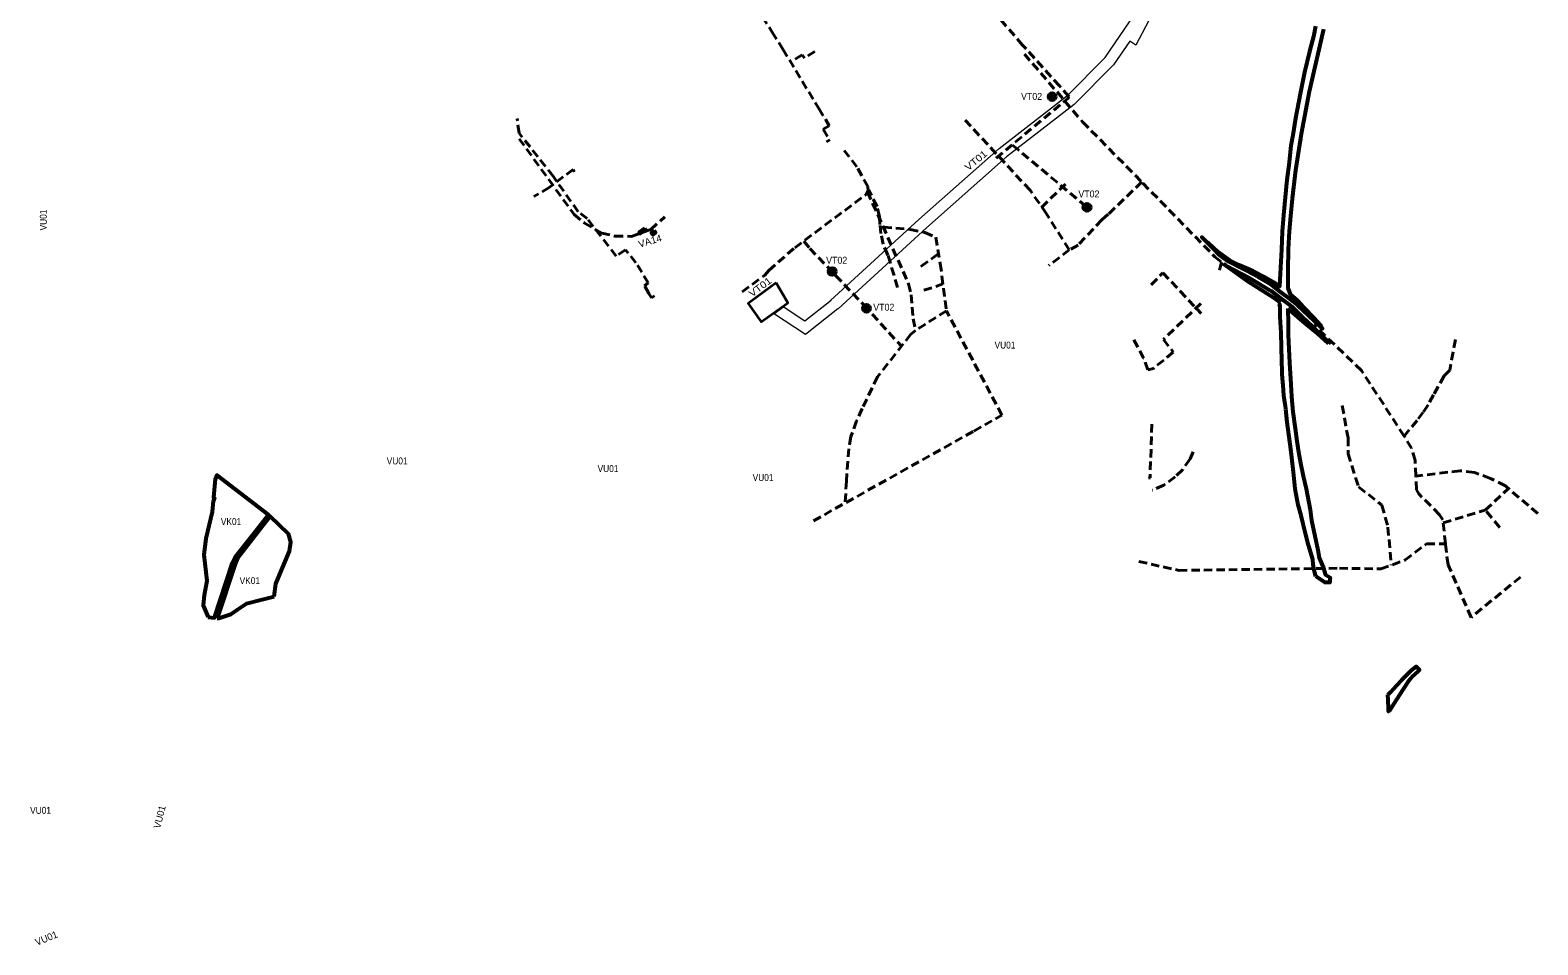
# Model space of a CAD drawing. Extents: x -650145 to -642675, y -1074338 to -1066724.
# Drawn here: x -648976 to -644627, y -1074338 to -1071699 of the extents above; entities that cross this region are included whole.
import ezdxf

# ---------------------------------------------------------------- set-up
doc = ezdxf.new("R2010")
doc.units = 0
doc.header["$LTSCALE"] = 8
doc.linetypes.add('MEDIUM_DASHED', pattern=[4.5, 3, -1.5])
for name, color, linetype in [('1', 7, 'Continuous'), ('17', 7, 'Continuous'), ('2', 7, 'Continuous'), ('3', 7, 'Continuous')]:
    doc.layers.add(name, color=color, linetype=linetype)
for name, color, linetype, lineweight in [('12', 7, 'MEDIUM_DASHED', 40), ('15', 7, 'Continuous', 13), ('45', 7, 'Continuous', 53), ('60', 7, 'Continuous', 53)]:
    doc.layers.add(name, color=color, linetype=linetype, lineweight=lineweight)

msp = doc.modelspace()

# ---------------------------------------------------------------- hatches: boundary and pattern name
at = {"layer": '15'}
for points in [[(-646016.453, -1071890.987, 1), (-646039.978, -1071890.987, 1)], [(-645916.109, -1072210.132, 1), (-645939.634, -1072210.132, 1)], [(-646651.182, -1072395.364, 1), (-646674.706, -1072395.364, 1)], [(-646551.973, -1072501.882, 1), (-646575.498, -1072501.882, 1)]]:
    msp.add_hatch(color=256, dxfattribs=at).paths.add_polyline_path(points)
at = {"layer": '60'}
for points in [[(-647203.48, -1072271.1), (-647219.86, -1072283.16), (-647217.95, -1072285.83), (-647201.52, -1072273.8)], [(-647175.95, -1072277.72), (-647183.77, -1072283.6), (-647179.89, -1072288.9), (-647172.06, -1072283.01)]]:
    msp.add_hatch(color=256, dxfattribs=at).paths.add_polyline_path(points)

# ---------------------------------------------------------------- linework, layer by layer
at = {"layer": '12'}
for p, q in [((-646142.308, -1072031.286), (-645934.368, -1072204.655)), ((-645990.194, -1072143.593), (-646067.454, -1072218.303)), ((-646406.679, -1072380.519), (-646355.921, -1072344.291)), ((-646398.36, -1072449.736), (-646343.369, -1072431.172)), ((-644737.523, -1073134.312), (-644778.948, -1073083.582))]:
    msp.add_line(p, q, dxfattribs=at)
for points in [[(-646901.7, -1071599.29), (-646836.01, -1071704.74), (-646804.94, -1071754.31)], [(-645979.173, -1071891.235), (-646007.318, -1071860.17), (-646113.522, -1071742.176), (-646203.196, -1071638.82), (-646210.712, -1071621.148)], [(-646804.94, -1071754.31), (-646701.24, -1071925.46), (-646671.37, -1071974.86)], [(-646712.71, -1071760.64), (-646743.06, -1071780.15), (-646749.35, -1071770.55), (-646782.673, -1071791.06)], [(-646108.34, -1071768.288), (-645991.774, -1071903.675), (-645940.8, -1071963.54), (-645766.873, -1072140.424), (-645559.153, -1072352.891), (-645539.728, -1072368.513), (-645547.013, -1072398.199)], [(-646190.163, -1072068.09), (-645983.794, -1071896.963), (-645979.173, -1071891.234)], [(-647369.65, -1072242.58), (-647395.603, -1072222.827), (-647467.645, -1072120.835), (-647565.59, -1071996.178), (-647571.937, -1071954.126)], [(-646671.37, -1071974.86), (-646688.66, -1071985.16), (-646669.77, -1072015.67), (-646679.35, -1072021.71)], [(-645978.908, -1072332.844), (-646044.53, -1072228.907), (-646091.859, -1072161.141), (-646284.4, -1071953.541)], [(-647565.274, -1072012.581), (-647407.42, -1072230.889), (-647378.312, -1072255.368), (-647327.486, -1072284.458), (-647289.597, -1072293.583), (-647241.628, -1072293.997), (-647186.201, -1072273.818), (-647145.51, -1072238.04)], [(-646922.495, -1072453.643), (-646857.191, -1072406.111), (-646845.696, -1072392.061), (-646770.684, -1072326.695), (-646564.651, -1072173.134), (-646559.323, -1072162.51), (-646560.242, -1072150.62), (-646591.477, -1072093.57), (-646627.948, -1072046.396)], [(-647405.694, -1072108.1), (-647409.897, -1072100.921), (-647478.896, -1072153.329), (-647523.403, -1072178.874)], [(-646515.621, -1072316.407), (-646522.296, -1072286.272), (-646525.05, -1072259.936), (-646526.73, -1072237.276), (-646533.563, -1072207.871), (-646557.282, -1072161.242)], [(-645770.117, -1072137.125), (-645867.081, -1072230.375), (-645887.539, -1072249.441)], [(-646560.829, -1072165.418), (-646442.617, -1072430.974), (-646435.336, -1072462.744), (-646429.379, -1072531.58), (-646422.811, -1072565.755), (-646435.637, -1072576.085), (-646531.76, -1072698.93), (-646576.398, -1072790.696), (-646592.362, -1072826.343), (-646608.607, -1072871.571), (-646614.559, -1072906.613), (-646622.02, -1072999.792), (-646625.456, -1073063.469)], [(-647191.37, -1072458.86), (-647204.41, -1072436.35), (-647193.17, -1072428.14), (-647228.9, -1072369.98), (-647259.29, -1072332.91), (-647286.03, -1072350.98), (-647368.027, -1072244.683)], [(-645884.618, -1072246.363), (-645953.602, -1072319.058), (-645978.908, -1072332.844), (-646038.138, -1072377.943)], [(-646515.068, -1072268.004), (-646438.375, -1072274.017), (-646395.81, -1072282.852), (-646364.347, -1072296.336), (-646351.055, -1072371.983), (-646333.32, -1072508.549)], [(-646744.92, -1072307.492), (-646727.261, -1072328.683), (-646572.036, -1072491.987), (-646462.937, -1072610.974)], [(-646474.01, -1072441.461), (-646502.208, -1072348.07), (-646515.621, -1072316.407)], [(-645742.473, -1072433.786), (-645709.258, -1072399.404), (-645598.422, -1072516.199)], [(-647175.32, -1072466), (-647184.36, -1072470.98), (-647191.37, -1072458.86)], [(-646716.85, -1073114.625), (-646254.197, -1072855.664), (-646173.155, -1072809.893), (-646333.32, -1072508.549), (-646422.811, -1072565.755)], [(-645599.642, -1072487.459), (-645707.673, -1072591.746), (-645678.856, -1072628.004), (-645736.077, -1072674.835), (-645752.766, -1072679.471), (-645764.412, -1072645.375), (-645793.32, -1072590.47)], [(-644677.063, -1073276.773), (-644820.09, -1073393.239), (-644886.431, -1073241.755), (-644894.218, -1073180.725), (-644901.367, -1073111.484), (-644910.953, -1073097.104), (-644970.414, -1073037.091), (-644977.617, -1073024.956), (-644979.519, -1072985.65), (-644981.225, -1072940.656), (-644991.691, -1072905.052), (-645013.264, -1072869.98), (-645136.284, -1072680.783), (-645273.573, -1072549.71)], [(-644865.163, -1072591.801), (-644881.47, -1072679.739), (-644897.776, -1072696.046), (-644928.014, -1072751.285)], [(-644928.014, -1072751.285), (-644944.228, -1072780.29), (-644958.247, -1072801.452), (-644975.175, -1072824.929), (-645013.264, -1072869.98)], [(-645191.679, -1072782.461), (-645175.001, -1072875.23), (-645175.001, -1072921.093), (-645144.773, -1073016.989), (-645077.02, -1073069.106), (-645059.861, -1073133.007), (-645050.18, -1073242.481)], [(-645740.627, -1072835.69), (-645745.906, -1072985.427), (-645745.265, -1072991.028), (-645750.784, -1072992.05)], [(-645621.405, -1072915.798), (-645630.523, -1072936.275), (-645652.44, -1072967.63), (-645673.716, -1072987.946), (-645706.351, -1073011.942), (-645739.675, -1073026.324)], [(-644627.418, -1073093.922), (-644720.94, -1073014.135), (-644763.53, -1072992.287), (-644810.544, -1072975.14), (-644851.751, -1072970.162), (-644979.519, -1072985.65)], [(-644900.454, -1073120.324), (-644778.948, -1073083.582), (-644712.07, -1073021.703)], [(-645777.988, -1073231.981), (-645662.45, -1073257.758), (-645199.545, -1073251.421), (-645080.605, -1073253.501), (-645010.848, -1073228.236), (-644948.284, -1073180.725), (-644894.218, -1073180.725)]]:
    msp.add_lwpolyline(points, dxfattribs=at)
at = {"layer": '15', "lineweight": 35}
msp.add_line((-646832.318, -1072516.145), (-646804.328, -1072496.262), dxfattribs=at)
at = {"layer": '15'}
for points in [[(-645985.984, -1071889.912), (-645875.751, -1071778.476), (-645805.025, -1071675.361), (-645627.872, -1071341.184), (-645225.385, -1071341.796), (-645184.278, -1071232.417)], [(-645184.278, -1071232.417), (-645183.56, -1071242.5), (-645178.87, -1071266.352), (-645207.234, -1071341.824), (-645170.274, -1071341.88), (-645167.04, -1071373.884), (-645592.784, -1071373.238), (-645786.781, -1071742.105), (-645804.579, -1071731.285)], [(-645804.579, -1071731.285), (-645850.985, -1071798.942), (-645964.716, -1071913.914)], [(-646668.175, -1072479.188), (-646413.327, -1072245.835), (-646181.43, -1072040.387), (-645987.337, -1071889.954)], [(-645964.715, -1071913.913), (-646159.64, -1072064.991), (-646390.555, -1072269.569), (-646645.209, -1072502.744)], [(-646646.125, -1072503.522), (-646739.733, -1072577.115), (-646832.318, -1072516.145), (-646804.328, -1072496.262)], [(-646804.328, -1072496.262), (-646741.387, -1072537.711), (-646665.903, -1072478.366)]]:
    msp.add_lwpolyline(points, dxfattribs=at)
at = {"layer": '15', "lineweight": 35}
msp.add_lwpolyline([(-646824.42, -1072428.58), (-646878.91, -1072468.54), (-646905.18, -1072487.8), (-646867.283, -1072540.984), (-646791.569, -1072487.198), (-646790.354, -1072486.136), (-646810.77, -1072451.09)], close=True, dxfattribs=at)
for centre in [(-646028.216, -1071890.987), (-645927.872, -1072210.132), (-646662.944, -1072395.364), (-646563.736, -1072501.882)]:
    msp.add_circle(centre, 11.762, dxfattribs=at)
at = {"layer": '45'}
msp.add_line((-645267.525, -1073275.443), (-645271.518, -1073261.16), dxfattribs=at)
for points in [[(-645269.077, -1071687.396), (-645274.868, -1071717.176), (-645286.175, -1071761.228), (-645300.076, -1071820.179), (-645313.153, -1071883.081), (-645326.343, -1071952.807), (-645334.118, -1072001.954), (-645339.455, -1072031.565), (-645344.819, -1072081.225), (-645351.358, -1072130.815), (-645361.317, -1072232.824), (-645364.435, -1072280.268), (-645366.951, -1072331.609), (-645370.624, -1072401.447), (-645372.228, -1072438.764), (-645387.894, -1072427.453), (-645401.441, -1072419.033), (-645414.631, -1072411.611), (-645448.831, -1072394.325), (-645488.64, -1072376.782), (-645515.437, -1072363.447), (-645547.593, -1072340.827), (-645577.33, -1072312.704), (-645579.217, -1072312.425), (-645596.405, -1072296.114), (-645564.4, -1072328.61), (-645547.72, -1072346.19), (-645532.07, -1072358.01), (-645531.65, -1072358.29), (-645528.27, -1072360.53), (-645519.57, -1072366.3), (-645438.64, -1072408.1), (-645437.6, -1072408.64), (-645434.19, -1072410.67), (-645399.77, -1072431.12), (-645371.356, -1072453.119), (-645342.284, -1072475.625), (-645333.62, -1072482.33), (-645290.76, -1072520.92), (-645271.74, -1072539.96), (-645249.9, -1072561.25), (-645248.967, -1072559.511), (-645252.768, -1072552.178), (-645265.009, -1072538.358), (-645272.276, -1072530.154), (-645302.303, -1072499.014), (-645320.805, -1072479.495), (-645339.904, -1072462.677), (-645347.551, -1072443.527), (-645347.677, -1072391.355), (-645346.62, -1072330.914), (-645343.458, -1072278.998), (-645339.908, -1072235.158), (-645335.367, -1072185.207), (-645325.498, -1072102.789), (-645309.01, -1071998.147), (-645285.617, -1071875.733), (-645244.798, -1071696.585)], [(-645462.646, -1072425.015), (-645534.301, -1072374.332), (-645533.08, -1072373.71)], [(-645533.08, -1072373.71), (-645527.33, -1072377.73), (-645459.31, -1072413.95), (-645456.52, -1072415.6), (-645400.12, -1072449.03), (-645396.94, -1072451.44), (-645370.226, -1072471.736)], [(-645369.364, -1072485.931), (-645389.731, -1072471.612), (-645462.646, -1072425.015)], [(-645364.524, -1072682.575), (-645366.022, -1072654.462), (-645368.173, -1072571.881), (-645370.755, -1072525.734), (-645370.928, -1072496.619), (-645372.72, -1072490.314), (-645369.364, -1072485.931)], [(-645370.226, -1072471.736), (-645362.81, -1072477.37), (-645345.079, -1072490.836)], [(-645347.292, -1072502.877), (-645348.253, -1072505.583), (-645347.214, -1072540.97), (-645347.795, -1072577.893), (-645344.152, -1072658.857), (-645339.96, -1072721.587), (-645338.023, -1072755.969), (-645333.718, -1072799.987)], [(-645230.845, -1072602.888), (-645263.217, -1072574.314), (-645298.498, -1072545.352), (-645347.292, -1072502.877)], [(-645345.079, -1072490.836), (-645336.33, -1072497.48), (-645306.46, -1072527.08), (-645276.93, -1072555.11), (-645263.7, -1072567.8), (-645242, -1072588.6), (-645241.87, -1072588.722), (-645228.96, -1072600.865), (-645230.845, -1072602.888)], [(-645357.272, -1072772.771), (-645359.76, -1072752.865), (-645361.874, -1072723.527), (-645362.708, -1072714.781), (-645364.786, -1072692.977), (-645364.524, -1072682.575)], [(-645271.518, -1073261.16), (-645272.747, -1073256.762), (-645275.269, -1073240.71), (-645276.125, -1073226.571), (-645288.647, -1073184.518), (-645297.395, -1073151.294), (-645310.558, -1073098.946), (-645319.052, -1073068.6), (-645327.554, -1073022.214), (-645332.517, -1072974.538), (-645337.34, -1072932.073), (-645340.345, -1072908.029), (-645350.822, -1072830.388), (-645354.019, -1072792.454), (-645355.121, -1072782.993), (-645357.272, -1072772.771)], [(-645333.718, -1072799.987), (-645327.091, -1072848.387), (-645322.284, -1072885.085), (-645317.65, -1072916.642)], [(-645317.65, -1072916.642), (-645311.772, -1072947.945), (-645304.24, -1072985.372), (-645295.788, -1073022.556)], [(-648463.25, -1073392.125), (-648444.523, -1073394.235), (-648392.43, -1073235.98), (-648384.6, -1073219.54), (-648315.955, -1073131.889), (-648289.148, -1073097.66), (-648437.643, -1072982.601), (-648442.187, -1072994.5), (-648447.043, -1073046.967), (-648444.11, -1073048.69), (-648448.1, -1073058.393)], [(-645295.788, -1073022.556), (-645284.269, -1073083.286), (-645279.878, -1073113.356), (-645262.388, -1073199.409), (-645257.842, -1073221.36), (-645247.051, -1073248.736), (-645239.9, -1073270.025), (-645226.847, -1073278.345), (-645227.199, -1073283.366), (-645227.744, -1073292.736), (-645241.72, -1073292.2), (-645263.03, -1073278.25), (-645267.525, -1073275.443)], [(-648448.1, -1073058.393), (-648450.875, -1073088.375), (-648469.875, -1073165.5), (-648475.437, -1073212.375), (-648466.687, -1073288.25), (-648474.5, -1073328.75), (-648477.562, -1073358.875), (-648463.25, -1073392.125)], [(-648272.642, -1073332.558), (-648268, -1073296), (-648261, -1073280), (-648228, -1073202), (-648224, -1073176), (-648231, -1073152), (-648283.884, -1073101.15), (-648311.798, -1073137.127), (-648378.17, -1073222.67), (-648385.09, -1073238.58), (-648436.857, -1073395.099)], [(-648397.062, -1073384.375), (-648378.125, -1073370.875), (-648352.312, -1073353), (-648314.687, -1073343.25), (-648272.642, -1073332.558)], [(-648436.857, -1073395.099), (-648432.187, -1073395.625), (-648397.062, -1073384.375)], [(-645060.009, -1073616.53), (-645051.513, -1073608.124), (-645035.303, -1073590.199), (-645020.11, -1073573.585), (-644993.044, -1073546.324), (-644977.924, -1073535.072), (-644969.117, -1073544.254), (-644985.66, -1073560.69), (-644996.41, -1073571.97), (-645001.267, -1073578.582), (-645015.55, -1073599.96), (-645043.35, -1073644.04), (-645056.06, -1073664.2)], [(-645056.06, -1073664.2), (-645057.87, -1073664.55), (-645058.01, -1073661.37), (-645058.42, -1073652.18), (-645058.65, -1073647), (-645058.96, -1073640.09), (-645059.35, -1073631.3), (-645060.009, -1073616.53)]]:
    msp.add_lwpolyline(points, dxfattribs=at)
at = {"layer": '60'}
for points in [[(-647203.48, -1072271.1), (-647219.86, -1072283.16), (-647217.95, -1072285.83), (-647201.52, -1072273.8)], [(-647175.95, -1072277.72), (-647183.77, -1072283.6), (-647179.89, -1072288.9), (-647172.06, -1072283.01)]]:
    msp.add_lwpolyline(points, close=True, dxfattribs=at)

# ---------------------------------------------------------------- texts
at = {"layer": '1', "width": 0.9}
for p in [(-648426.286, -1073126.802), (-648372.004, -1073297.285)]:
    msp.add_text('VK01', height=20, dxfattribs=at).set_placement(p)
at = {"layer": '17', "width": 0.95}
for p in [(-646118.047, -1071900.373), (-645952.7, -1072181.661), (-646680.229, -1072372.978), (-646544.334, -1072508.451)]:
    msp.add_text('VT02', height=20, dxfattribs=at).set_placement(p)
at = {"layer": '17', "width": 1.15}
for rotation, p in [(39.483, (-646270.392, -1072106.216)), (37.163, (-646893.836, -1072470.401))]:
    msp.add_text('VT01', height=20, rotation=rotation, dxfattribs=at).set_placement(p)
at = {"layer": '2', "width": 0.9}
msp.add_text('VU01', height=20, rotation=90, dxfattribs=at).set_placement((-648928.323, -1072276.985))
for p in [(-646194.406, -1072617.656), (-647947.746, -1072951.906), (-647339.543, -1072974.017), (-646892.266, -1072999.605), (-648976.371, -1073959.861)]:
    msp.add_text('VU01', height=20, dxfattribs=at).set_placement(p)
at = {"layer": '2'}
for rotation, p in [(75.792, (-648601.32, -1074003.735)), (22.398, (-648956.62, -1074340.801))]:
    msp.add_text('VU01', height=20, rotation=rotation, dxfattribs=at).set_placement(p)
at = {"layer": '3', "width": 1.05}
msp.add_text('VA14', height=20, rotation=16.632, dxfattribs=at).set_placement((-647218.51, -1072326.887))

doc.saveas('drawing.dxf')
